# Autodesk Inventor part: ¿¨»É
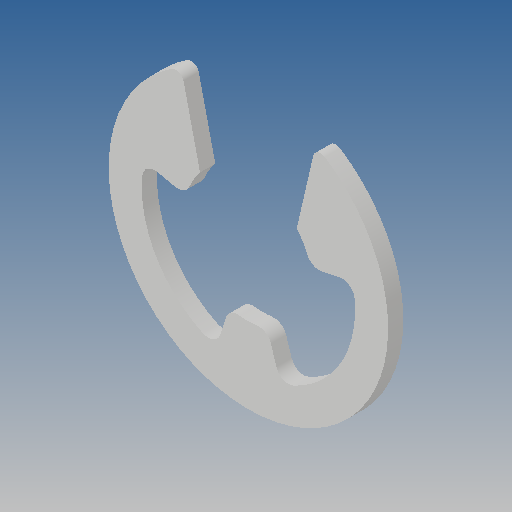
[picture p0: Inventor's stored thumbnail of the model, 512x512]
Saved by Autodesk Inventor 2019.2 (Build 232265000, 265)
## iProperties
Created: 2013-07
Part Number: ¿¨»É
Material: Ogólny
Document SubType Name: Modeling
Designer: CADENGINEERING4
Density: 1 g/cm^3
Appearance: Domyślna
Author: CADENGINEERING4
Revision Number: ÈÎºÎ
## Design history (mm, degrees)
feature "Í¹Ì¨-À­Éì1"
node "Bryła1"
